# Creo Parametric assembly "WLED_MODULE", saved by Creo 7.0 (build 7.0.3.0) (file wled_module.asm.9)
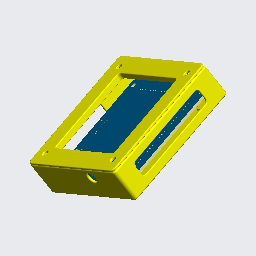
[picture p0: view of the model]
Units: millimeter Kilogram Sec (mmKs); MM, KILOGRAM, SECS

Created from: XX_MMKS_ASM_DESIGN_ABS.ASM

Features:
  1. datum plane "ASM_RIGHT"
  2. datum plane "ASM_TOP"
  3. datum plane "ASM_FRONT"
  4. coordinate system
  5. component "WLED_BOX"
  6. component "NEOLIGHT_PCB"
  7. component "WLED_COVER_0"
